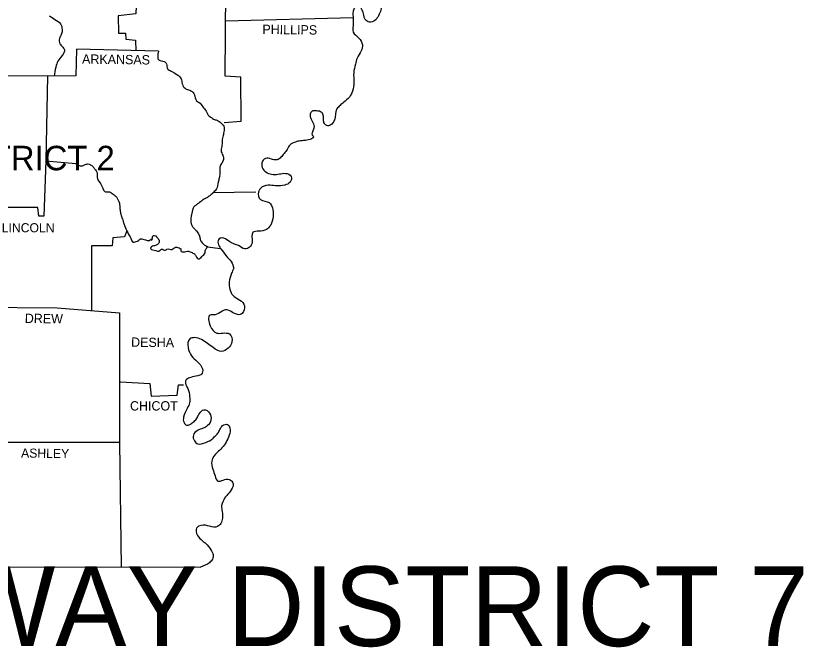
# Model space of a CAD drawing. Extents: x 3046 to 131673, y -8885 to 10756.
# Drawn here: x 105176 to 108727, y 4715 to 7566 of the extents above; entities that cross this region are included whole.
import ezdxf

# ---------------------------------------------------------------- set-up
doc = ezdxf.new("R2010")
doc.units = 0
for name, color, linetype in [('1', 7, 'Continuous'), ('2', 7, 'Continuous'), ('3', 7, 'Continuous')]:
    doc.layers.add(name, color=color, linetype=linetype)

msp = doc.modelspace()

# ---------------------------------------------------------------- linework, layer by layer
at = {"layer": '1'}
msp.add_line((106063.3, 6768.2), (106259, 6771.2), dxfattribs=at)
msp.add_line((106063.3, 6768.2), (106259, 6771.2), dxfattribs=at)
for points in [[(106116.1, 7084.2), (106192.4, 7089.1), (106191.5, 7287.8), (106120, 7292.6), (106123.9, 7681.1), (106062.3, 7689.9), (106060.4, 7951.1), (106899.7, 7957)], [(106116.1, 7084.2), (106192.4, 7089.1), (106191.5, 7287.8), (106120, 7292.6), (106123.9, 7681.1), (106062.3, 7689.9), (106060.4, 7951.1), (106899.7, 7957)], [(105729.7, 7842.5), (105717.9, 7574.4), (105637.7, 7565.6), (105639.6, 7486.4), (105671.9, 7487.3), (105672.9, 7460), (105716.9, 7455.1), (105718.4, 7407.8)], [(105729.7, 7842.5), (105717.9, 7574.4), (105637.7, 7565.6), (105639.6, 7486.4), (105671.9, 7487.3), (105672.9, 7460), (105716.9, 7455.1), (105718.4, 7407.8)], [(106122.6, 7543), (106697.4, 7557.3)], [(106122.6, 7543), (106697.4, 7557.3)], [(105819.7, 7405.2), (105449.8, 7414.9), (105447.9, 7294.6), (104699.4, 7291.7)], [(105819.7, 7405.2), (105449.8, 7414.9), (105447.9, 7294.6), (104699.4, 7291.7)], [(105319.8, 7294.1), (105311.9, 6910.1), (105447.9, 6899.3)], [(105319.8, 7294.1), (105311.9, 6910.1), (105447.9, 6899.3)], [(105311.9, 6910.1), (105303.1, 6661.6), (105280.6, 6661.6), (105276.6, 6699.7), (105016.4, 6699.7), (105016.4, 6644.9)], [(105311.9, 6910.1), (105303.1, 6661.6), (105280.6, 6661.6), (105276.6, 6699.7), (105016.4, 6699.7), (105016.4, 6644.9)], [(105677.8, 6594.1), (105666.1, 6567.6), (105614.2, 6562.8), (105611.3, 6527.5), (105518.3, 6527.5), (105517.3, 6235)], [(105677.8, 6594.1), (105666.1, 6567.6), (105614.2, 6562.8), (105611.3, 6527.5), (105518.3, 6527.5), (105517.3, 6235)], [(105787.4, 6551), (105790.3, 6553.9), (105793.2, 6556.9), (105793.2, 6556.9)], [(105787.4, 6551), (105790.3, 6553.9), (105793.2, 6556.9), (105793.2, 6556.9)], [(104999.8, 6249.7), (105362.7, 6246.7), (105644.5, 6225.2)], [(104999.8, 6249.7), (105362.7, 6246.7), (105644.5, 6225.2)], [(105644.5, 6225.2), (105644.5, 5640.1), (105652.4, 5077.5)], [(105644.5, 6225.2), (105644.5, 5640.1), (105652.4, 5077.5)], [(105649.4, 5913.1), (105780.5, 5905.3), (105786.4, 5848.5), (105904.8, 5852.4), (105909.7, 5900.4), (105932.2, 5900.4)], [(105649.4, 5913.1), (105780.5, 5905.3), (105786.4, 5848.5), (105904.8, 5852.4), (105909.7, 5900.4), (105932.2, 5900.4)], [(102421.7, 5874.9), (102423.6, 5083.4), (106009.5, 5077.5)], [(102421.7, 5874.9), (102423.6, 5083.4), (106009.5, 5077.5)], [(105002.3, 5641.1), (105644.5, 5641.1)], [(105002.3, 5641.1), (105644.5, 5641.1)]]:
    msp.add_lwpolyline(points, dxfattribs=at)
for points in [[(106833.3, 7720.2), (106810.8, 7691.8), (106777.5, 7709.4), (106777.5, 7732.9), (106782.4, 7757.4), (106770.7, 7773), (106750.1, 7766.2), (106750.1, 7735.9), (106748.2, 7706.5), (106742.3, 7664.4), (106756, 7651.7), (106787.3, 7647.8), (106809.8, 7641.9), (106823.5, 7619.4), (106822.5, 7592), (106811.8, 7565.6), (106796.1, 7544.1), (106771.7, 7536.3), (106752.1, 7549), (106744.3, 7574.4), (106735.5, 7596.9), (106718.8, 7613.6), (106701.2, 7595), (106697.3, 7560.7), (106698.3, 7531.4), (106698.3, 7491.3), (106723.7, 7464.8), (106739.4, 7434.5), (106734.5, 7407.1), (106715.9, 7374.8), (106708.1, 7346.5), (106700.2, 7308.3), (106701.2, 7266.2), (106694.4, 7225.1), (106680.7, 7197.7), (106655.2, 7175.2), (106638.6, 7160.6), (106624.9, 7145.9), (106618, 7116.5), (106613.2, 7096), (106594.6, 7071.5), (106579.9, 7069.6), (106568.1, 7079.4), (106564.2, 7096), (106564.2, 7112.6), (106556.4, 7129.3), (106531.9, 7136.1), (106512.4, 7135.1), (106503.6, 7121.4), (106516.3, 7083.3), (106521.2, 7058.8), (106514.3, 7025.5), (106518.2, 7021.6), (106483, 7003), (106454.7, 7000.1), (106431.2, 6993.3), (106408.7, 6978.6), (106397.9, 6957.1), (106382.2, 6939.4), (106368.6, 6922.8), (106350, 6915), (106329.4, 6918.9), (106302, 6921.8), (106286.4, 6902.3), (106291.3, 6873.9), (106309.8, 6857.3), (106337.2, 6849.4), (106365.6, 6851.4), (106393, 6854.3), (106418.4, 6840.6), (106413.6, 6814.2), (106389.1, 6801.5), (106352.9, 6797.6), (106323.5, 6800.5), (106288.3, 6792.7), (106270.7, 6770.2), (106280.5, 6735.9), (106318.7, 6722.2), (106336.3, 6689.9), (106337.2, 6659.6), (106324.5, 6619.5), (106306.9, 6600.9), (106272.7, 6593.1), (106246.2, 6588.2), (106242.3, 6543.2), (106230.6, 6520.7), (106210, 6513.8), (106180.7, 6528.5), (106163.1, 6535.4), (106141.6, 6545.1), (106114.2, 6561.8), (106093.6, 6558.8), (106099.5, 6515.8), (106101.4, 6513.8), (106124.9, 6481.5), (106148.4, 6456.1), (106159.2, 6425.8)], [(106833.3, 7720.2), (106810.8, 7691.8), (106777.5, 7709.4), (106777.5, 7732.9), (106782.4, 7757.4), (106770.7, 7773), (106750.1, 7766.2), (106750.1, 7735.9), (106748.2, 7706.5), (106742.3, 7664.4), (106756, 7651.7), (106787.3, 7647.8), (106809.8, 7641.9), (106823.5, 7619.4), (106822.5, 7592), (106811.8, 7565.6), (106796.1, 7544.1), (106771.7, 7536.3), (106752.1, 7549), (106744.3, 7574.4), (106735.5, 7596.9), (106718.8, 7613.6), (106701.2, 7595), (106697.3, 7560.7), (106698.3, 7531.4), (106698.3, 7491.3), (106723.7, 7464.8), (106739.4, 7434.5), (106734.5, 7407.1), (106715.9, 7374.8), (106708.1, 7346.5), (106700.2, 7308.3), (106701.2, 7266.2), (106694.4, 7225.1), (106680.7, 7197.7), (106655.2, 7175.2), (106638.6, 7160.6), (106624.9, 7145.9), (106618, 7116.5), (106613.2, 7096), (106594.6, 7071.5), (106579.9, 7069.6), (106568.1, 7079.4), (106564.2, 7096), (106564.2, 7112.6), (106556.4, 7129.3), (106531.9, 7136.1), (106512.4, 7135.1), (106503.6, 7121.4), (106516.3, 7083.3), (106521.2, 7058.8), (106514.3, 7025.5), (106518.2, 7021.6), (106483, 7003), (106454.7, 7000.1), (106431.2, 6993.3), (106408.7, 6978.6), (106397.9, 6957.1), (106382.2, 6939.4), (106368.6, 6922.8), (106350, 6915), (106329.4, 6918.9), (106302, 6921.8), (106286.4, 6902.3), (106291.3, 6873.9), (106309.8, 6857.3), (106337.2, 6849.4), (106365.6, 6851.4), (106393, 6854.3), (106418.4, 6840.6), (106413.6, 6814.2), (106389.1, 6801.5), (106352.9, 6797.6), (106323.5, 6800.5), (106288.3, 6792.7), (106270.7, 6770.2), (106280.5, 6735.9), (106318.7, 6722.2), (106336.3, 6689.9), (106337.2, 6659.6), (106324.5, 6619.5), (106306.9, 6600.9), (106272.7, 6593.1), (106246.2, 6588.2), (106242.3, 6543.2), (106230.6, 6520.7), (106210, 6513.8), (106180.7, 6528.5), (106163.1, 6535.4), (106141.6, 6545.1), (106114.2, 6561.8), (106093.6, 6558.8), (106099.5, 6515.8), (106101.4, 6513.8), (106124.9, 6481.5), (106148.4, 6456.1), (106159.2, 6425.8)], [(105328.5, 7565.6), (105353, 7549), (105378.4, 7529.4), (105385.3, 7503), (105383.3, 7484.4), (105375.5, 7468.8), (105373.5, 7444.3), (105385.3, 7426.7), (105396, 7412), (105385.3, 7385.6), (105366.7, 7361.1), (105356.9, 7333.7), (105350, 7292.6)], [(105328.5, 7565.6), (105353, 7549), (105378.4, 7529.4), (105385.3, 7503), (105383.3, 7484.4), (105375.5, 7468.8), (105373.5, 7444.3), (105385.3, 7426.7), (105396, 7412), (105385.3, 7385.6), (105366.7, 7361.1), (105356.9, 7333.7), (105350, 7292.6)], [(105819.7, 7405.2), (105822.6, 7365), (105846.1, 7359.2), (105855.9, 7348.4), (105860.8, 7325.9), (105877.4, 7316.1), (105899.9, 7302.4), (105913.6, 7292.6), (105923.4, 7277), (105929.2, 7251.6), (105944.9, 7234.9), (105966.4, 7227.1), (105982.1, 7208.5), (105991.9, 7182.1), (106007.5, 7170.3), (106023.2, 7149.8), (106031, 7141), (106044.7, 7117.5), (106058.4, 7105.8), (106068.2, 7098.9), (106083.8, 7094), (106103.4, 7081.3), (106116.1, 7061.7), (106116.1, 7047.1), (106111.2, 7024.6), (106107.3, 7001.1), (106105.4, 6974.7), (106103.4, 6951.2), (106112.2, 6931.6), (106107.3, 6902.3), (106097.5, 6886.6), (106096.6, 6865.1), (106093.6, 6832.8), (106089.7, 6814.2), (106080.9, 6783.9), (106068.2, 6768.2)], [(105819.7, 7405.2), (105822.6, 7365), (105846.1, 7359.2), (105855.9, 7348.4), (105860.8, 7325.9), (105877.4, 7316.1), (105899.9, 7302.4), (105913.6, 7292.6), (105923.4, 7277), (105929.2, 7251.6), (105944.9, 7234.9), (105966.4, 7227.1), (105982.1, 7208.5), (105991.9, 7182.1), (106007.5, 7170.3), (106023.2, 7149.8), (106031, 7141), (106044.7, 7117.5), (106058.4, 7105.8), (106068.2, 7098.9), (106083.8, 7094), (106103.4, 7081.3), (106116.1, 7061.7), (106116.1, 7047.1), (106111.2, 7024.6), (106107.3, 7001.1), (106105.4, 6974.7), (106103.4, 6951.2), (106112.2, 6931.6), (106107.3, 6902.3), (106097.5, 6886.6), (106096.6, 6865.1), (106093.6, 6832.8), (106089.7, 6814.2), (106080.9, 6783.9), (106068.2, 6768.2)], [(105447.9, 6899.3), (105462.5, 6889.5), (105483.1, 6890.5), (105496.8, 6896.4), (105507.6, 6895.4), (105522.2, 6886.6), (105532, 6874.9), (105538.9, 6866.1), (105543.8, 6852.4), (105543.8, 6839.6), (105548.6, 6822), (105554.5, 6815.2), (105562.3, 6802.5), (105567.2, 6790.7), (105570.2, 6782.9), (105580.9, 6770.2), (105590.7, 6771.2), (105599.5, 6770.2), (105611.3, 6763.3), (105628.9, 6749.6), (105631.8, 6745.7), (105643.6, 6720.3), (105645.5, 6704.6), (105647.5, 6684.1), (105651.4, 6664.5), (105659.2, 6643), (105663.1, 6628.3), (105671.9, 6607.8), (105677.8, 6594.1), (105685.6, 6576.5), (105697.4, 6556.9), (105702.3, 6545.1), (105718.9, 6546.1), (105730.6, 6551), (105739.4, 6558.8), (105750.2, 6557.9), (105761.9, 6553.9), (105777.6, 6551), (105787.4, 6556.9), (105792.3, 6560.8), (105793.2, 6569.6), (105802.1, 6574.5), (105811.8, 6567.6), (105822.6, 6552), (105822.6, 6542.2), (105818.7, 6536.3), (105806, 6528.5), (105788.4, 6522.6), (105783.5, 6515.8), (105800.1, 6508), (105826.5, 6506), (105833.4, 6511.9), (105851, 6507), (105857.8, 6511.9), (105881.3, 6510.9), (105892.1, 6518.7), (105913.6, 6517.7), (105920.4, 6512.9), (105920.4, 6504.1), (105938.1, 6500.1), (105950.8, 6503.1), (105967.4, 6498.2), (105982.1, 6490.4), (105989.9, 6479.6), (105999.7, 6467.8), (106008.5, 6470.8), (106015.3, 6479.6), (106030, 6495.2), (106030, 6505), (106033.9, 6511.9), (106040.3, 6524.7)], [(105447.9, 6899.3), (105462.5, 6889.5), (105483.1, 6890.5), (105496.8, 6896.4), (105507.6, 6895.4), (105522.2, 6886.6), (105532, 6874.9), (105538.9, 6866.1), (105543.8, 6852.4), (105543.8, 6839.6), (105548.6, 6822), (105554.5, 6815.2), (105562.3, 6802.5), (105567.2, 6790.7), (105570.2, 6782.9), (105580.9, 6770.2), (105590.7, 6771.2), (105599.5, 6770.2), (105611.3, 6763.3), (105628.9, 6749.6), (105631.8, 6745.7), (105643.6, 6720.3), (105645.5, 6704.6), (105647.5, 6684.1), (105651.4, 6664.5), (105659.2, 6643), (105663.1, 6628.3), (105671.9, 6607.8), (105677.8, 6594.1), (105685.6, 6576.5), (105697.4, 6556.9), (105702.3, 6545.1), (105718.9, 6546.1), (105730.6, 6551), (105739.4, 6558.8), (105750.2, 6557.9), (105761.9, 6553.9), (105777.6, 6551), (105787.4, 6556.9), (105792.3, 6560.8), (105793.2, 6569.6), (105802.1, 6574.5), (105811.8, 6567.6), (105822.6, 6552), (105822.6, 6542.2), (105818.7, 6536.3), (105806, 6528.5), (105788.4, 6522.6), (105783.5, 6515.8), (105800.1, 6508), (105826.5, 6506), (105833.4, 6511.9), (105851, 6507), (105857.8, 6511.9), (105881.3, 6510.9), (105892.1, 6518.7), (105913.6, 6517.7), (105920.4, 6512.9), (105920.4, 6504.1), (105938.1, 6500.1), (105950.8, 6503.1), (105967.4, 6498.2), (105982.1, 6490.4), (105989.9, 6479.6), (105999.7, 6467.8), (106008.5, 6470.8), (106015.3, 6479.6), (106030, 6495.2), (106030, 6505), (106033.9, 6511.9), (106040.3, 6524.7)], [(106068.2, 6768.2), (106061.6, 6762.1), (106054.9, 6756.3), (106048, 6750.8), (106040.8, 6745.7), (106036.4, 6743.2), (106031.9, 6740.9), (106027.4, 6738.6), (106023.2, 6735.9), (106004.6, 6722.2), (105993.3, 6713.9), (105987.7, 6709.8), (105982.1, 6705.6), (105977.3, 6700), (105974.6, 6692.9), (105972.9, 6685), (105972.2, 6681.1), (105971.3, 6677.2), (105970.1, 6672.4), (105968.9, 6667.5), (105967, 6657.6), (105965.7, 6647.8), (105965.5, 6643), (105965.4, 6638.1), (105966.1, 6632), (105967.6, 6626), (105970, 6620.2), (105971.5, 6617.4), (105973.3, 6614.6), (105977.6, 6609.1), (105982.1, 6604.1), (105986.6, 6599.2), (105990.9, 6594.1), (105997, 6585.9), (106002.6, 6577.4), (106004.3, 6574.1), (106005.5, 6570.5), (106007, 6562.9), (106008.5, 6555.2), (106009.7, 6551.5), (106010.5, 6549.8), (106011.4, 6548.1), (106013.6, 6544.9), (106020.9, 6536.5), (106026.6, 6531.7), (106031.3, 6528.5), (106033, 6527.5), (106038.1, 6524.9), (106043.3, 6522.8)], [(106068.2, 6768.2), (106061.6, 6762.1), (106054.9, 6756.3), (106048, 6750.8), (106040.8, 6745.7), (106036.4, 6743.2), (106031.9, 6740.9), (106027.4, 6738.6), (106023.2, 6735.9), (106004.6, 6722.2), (105993.3, 6713.9), (105987.7, 6709.8), (105982.1, 6705.6), (105977.3, 6700), (105974.6, 6692.9), (105972.9, 6685), (105972.2, 6681.1), (105971.3, 6677.2), (105970.1, 6672.4), (105968.9, 6667.5), (105967, 6657.6), (105965.7, 6647.8), (105965.5, 6643), (105965.4, 6638.1), (105966.1, 6632), (105967.6, 6626), (105970, 6620.2), (105971.5, 6617.4), (105973.3, 6614.6), (105977.6, 6609.1), (105982.1, 6604.1), (105986.6, 6599.2), (105990.9, 6594.1), (105997, 6585.9), (106002.6, 6577.4), (106004.3, 6574.1), (106005.5, 6570.5), (106007, 6562.9), (106008.5, 6555.2), (106009.7, 6551.5), (106010.5, 6549.8), (106011.4, 6548.1), (106013.6, 6544.9), (106020.9, 6536.5), (106026.6, 6531.7), (106031.3, 6528.5), (106033, 6527.5), (106038.1, 6524.9), (106043.3, 6522.8)], [(106159.2, 6425.8), (106149.4, 6403.3), (106138.6, 6364.1), (106141.6, 6330.9), (106156.2, 6302.5), (106179.7, 6286.8), (106205.2, 6264.3), (106203.2, 6230.1), (106188.5, 6217.4), (106154.3, 6226.2), (106127.9, 6237.9), (106105.4, 6231.1), (106075, 6216.4), (106052.5, 6213.5), (106053.5, 6166.5), (106083.8, 6133.2), (106110.3, 6133.2), (106140.6, 6129.3), (106151.3, 6094.1), (106133.7, 6064.7), (106104.4, 6050.1), (106067.2, 6067.7), (106040.8, 6086.3), (106014.4, 6103.9), (105981.1, 6112.7), (105962.5, 6108.8), (105953.7, 6067.7), (105969.4, 6030.5), (105994.8, 6005.1), (106018.3, 5971.8), (106014.4, 5947.3), (105996.8, 5940.5), (105965.4, 5933.6), (105946.9, 5923.9), (105942, 5916), (105951.7, 5882.8), (105960.6, 5846.6), (105960.6, 5819.2), (105949.8, 5793.7), (105933.2, 5754.6), (105935.1, 5729.2), (105946.9, 5717.4), (105961.5, 5721.3), (105981.1, 5735), (105993.8, 5750.7), (106004.6, 5770.2), (106025.1, 5786.9), (106050.6, 5772.2), (106056.4, 5741.9), (106041.8, 5715.5), (106021.2, 5703.7), (105995.8, 5693.9), (105977.2, 5672.4), (105982.1, 5647), (105996.8, 5633.3), (106033, 5640.1), (106057.4, 5650.9), (106071.1, 5664.6), (106087.7, 5681.2), (106096.6, 5697.8), (106109.3, 5715.5), (106131.8, 5720.3), (106142.5, 5705.7), (106138.6, 5672.4), (106124.9, 5641.1), (106106.3, 5614.7), (106085.8, 5596.1), (106060.4, 5556), (106065.2, 5518.8), (106075, 5488.5), (106088.7, 5465), (106112.2, 5469.9), (106138.6, 5472.8), (106154.3, 5460.1), (106152.3, 5432.7), (106132.8, 5406.3), (106114.2, 5380.8), (106104.4, 5345.6), (106108.3, 5321.2), (106108.3, 5298.7), (106100.5, 5274.2), (106086.8, 5260.5), (106050.6, 5261.5), (106012.4, 5265.4), (105991.9, 5253.6), (105995.8, 5220.4), (106018.3, 5195.9), (106033.9, 5183.2), (106056.4, 5155.8), (106066.2, 5133.3), (106063.3, 5113.7), (106049.6, 5097.1), (106009.5, 5077.5)], [(106159.2, 6425.8), (106149.4, 6403.3), (106138.6, 6364.1), (106141.6, 6330.9), (106156.2, 6302.5), (106179.7, 6286.8), (106205.2, 6264.3), (106203.2, 6230.1), (106188.5, 6217.4), (106154.3, 6226.2), (106127.9, 6237.9), (106105.4, 6231.1), (106075, 6216.4), (106052.5, 6213.5), (106053.5, 6166.5), (106083.8, 6133.2), (106110.3, 6133.2), (106140.6, 6129.3), (106151.3, 6094.1), (106133.7, 6064.7), (106104.4, 6050.1), (106067.2, 6067.7), (106040.8, 6086.3), (106014.4, 6103.9), (105981.1, 6112.7), (105962.5, 6108.8), (105953.7, 6067.7), (105969.4, 6030.5), (105994.8, 6005.1), (106018.3, 5971.8), (106014.4, 5947.3), (105996.8, 5940.5), (105965.4, 5933.6), (105946.9, 5923.9), (105942, 5916), (105951.7, 5882.8), (105960.6, 5846.6), (105960.6, 5819.2), (105949.8, 5793.7), (105933.2, 5754.6), (105935.1, 5729.2), (105946.9, 5717.4), (105961.5, 5721.3), (105981.1, 5735), (105993.8, 5750.7), (106004.6, 5770.2), (106025.1, 5786.9), (106050.6, 5772.2), (106056.4, 5741.9), (106041.8, 5715.5), (106021.2, 5703.7), (105995.8, 5693.9), (105977.2, 5672.4), (105982.1, 5647), (105996.8, 5633.3), (106033, 5640.1), (106057.4, 5650.9), (106071.1, 5664.6), (106087.7, 5681.2), (106096.6, 5697.8), (106109.3, 5715.5), (106131.8, 5720.3), (106142.5, 5705.7), (106138.6, 5672.4), (106124.9, 5641.1), (106106.3, 5614.7), (106085.8, 5596.1), (106060.4, 5556), (106065.2, 5518.8), (106075, 5488.5), (106088.7, 5465), (106112.2, 5469.9), (106138.6, 5472.8), (106154.3, 5460.1), (106152.3, 5432.7), (106132.8, 5406.3), (106114.2, 5380.8), (106104.4, 5345.6), (106108.3, 5321.2), (106108.3, 5298.7), (106100.5, 5274.2), (106086.8, 5260.5), (106050.6, 5261.5), (106012.4, 5265.4), (105991.9, 5253.6), (105995.8, 5220.4), (106018.3, 5195.9), (106033.9, 5183.2), (106056.4, 5155.8), (106066.2, 5133.3), (106063.3, 5113.7), (106049.6, 5097.1), (106009.5, 5077.5)]]:
    msp.add_spline(points, degree=3, dxfattribs=at)
at = {"layer": '3'}
msp.add_line((106043.3, 6522.8), (106098.5, 6515.8), dxfattribs=at)
msp.add_line((106043.3, 6522.8), (106098.5, 6515.8), dxfattribs=at)

# ---------------------------------------------------------------- texts
at = {"layer": '2'}
for s, height, rotation, p in [('PHILLIPS', 42.06, 359.3179, (106288.3, 7483.4)), ('PHILLIPS', 42.06, 359.3179, (106288.3, 7483.4)), ('ARKANSAS', 42.06, 359.2678, (105475.3, 7349.4)), ('ARKANSAS', 42.06, 359.2678, (105475.3, 7349.4)), ('DREW', 42.06, 359.2258, (105217, 6179.2)), ('DREW', 42.06, 359.2258, (105217, 6179.2)), ('DESHA', 42.06, 359.3704, (105696.4, 6071.6)), ('DESHA', 42.06, 359.3704, (105696.4, 6071.6)), ('ASHLEY', 41.09, 359.2361, (105200.3, 5571.6)), ('ASHLEY', 41.09, 359.2361, (105200.3, 5571.6))]:
    msp.add_text(s, height=height, rotation=rotation, dxfattribs=at).set_placement(p)
for s, height, p in [('LINCOLN', 41.09, (105113.3, 6588.2)), ('LINCOLN', 41.09, (105113.3, 6588.2)), ('CHICOT', 42.07, (105691.5, 5783.9)), ('CHICOT', 42.07, (105691.5, 5783.9)), ('ARKANSAS HIGHWAY DISTRICT 7', 360, (100941.1, 4720.5))]:
    msp.add_text(s, height=height, dxfattribs=at).set_placement(p)
at = {"layer": '3'}
msp.add_text('DISTRICT 2', height=110.56, dxfattribs=at).set_placement((104817.8, 6868))
msp.add_text('DISTRICT 2', height=110.56, dxfattribs=at).set_placement((104817.8, 6868))

doc.saveas('drawing.dxf')
